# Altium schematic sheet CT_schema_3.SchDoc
size 293 x 258 mm
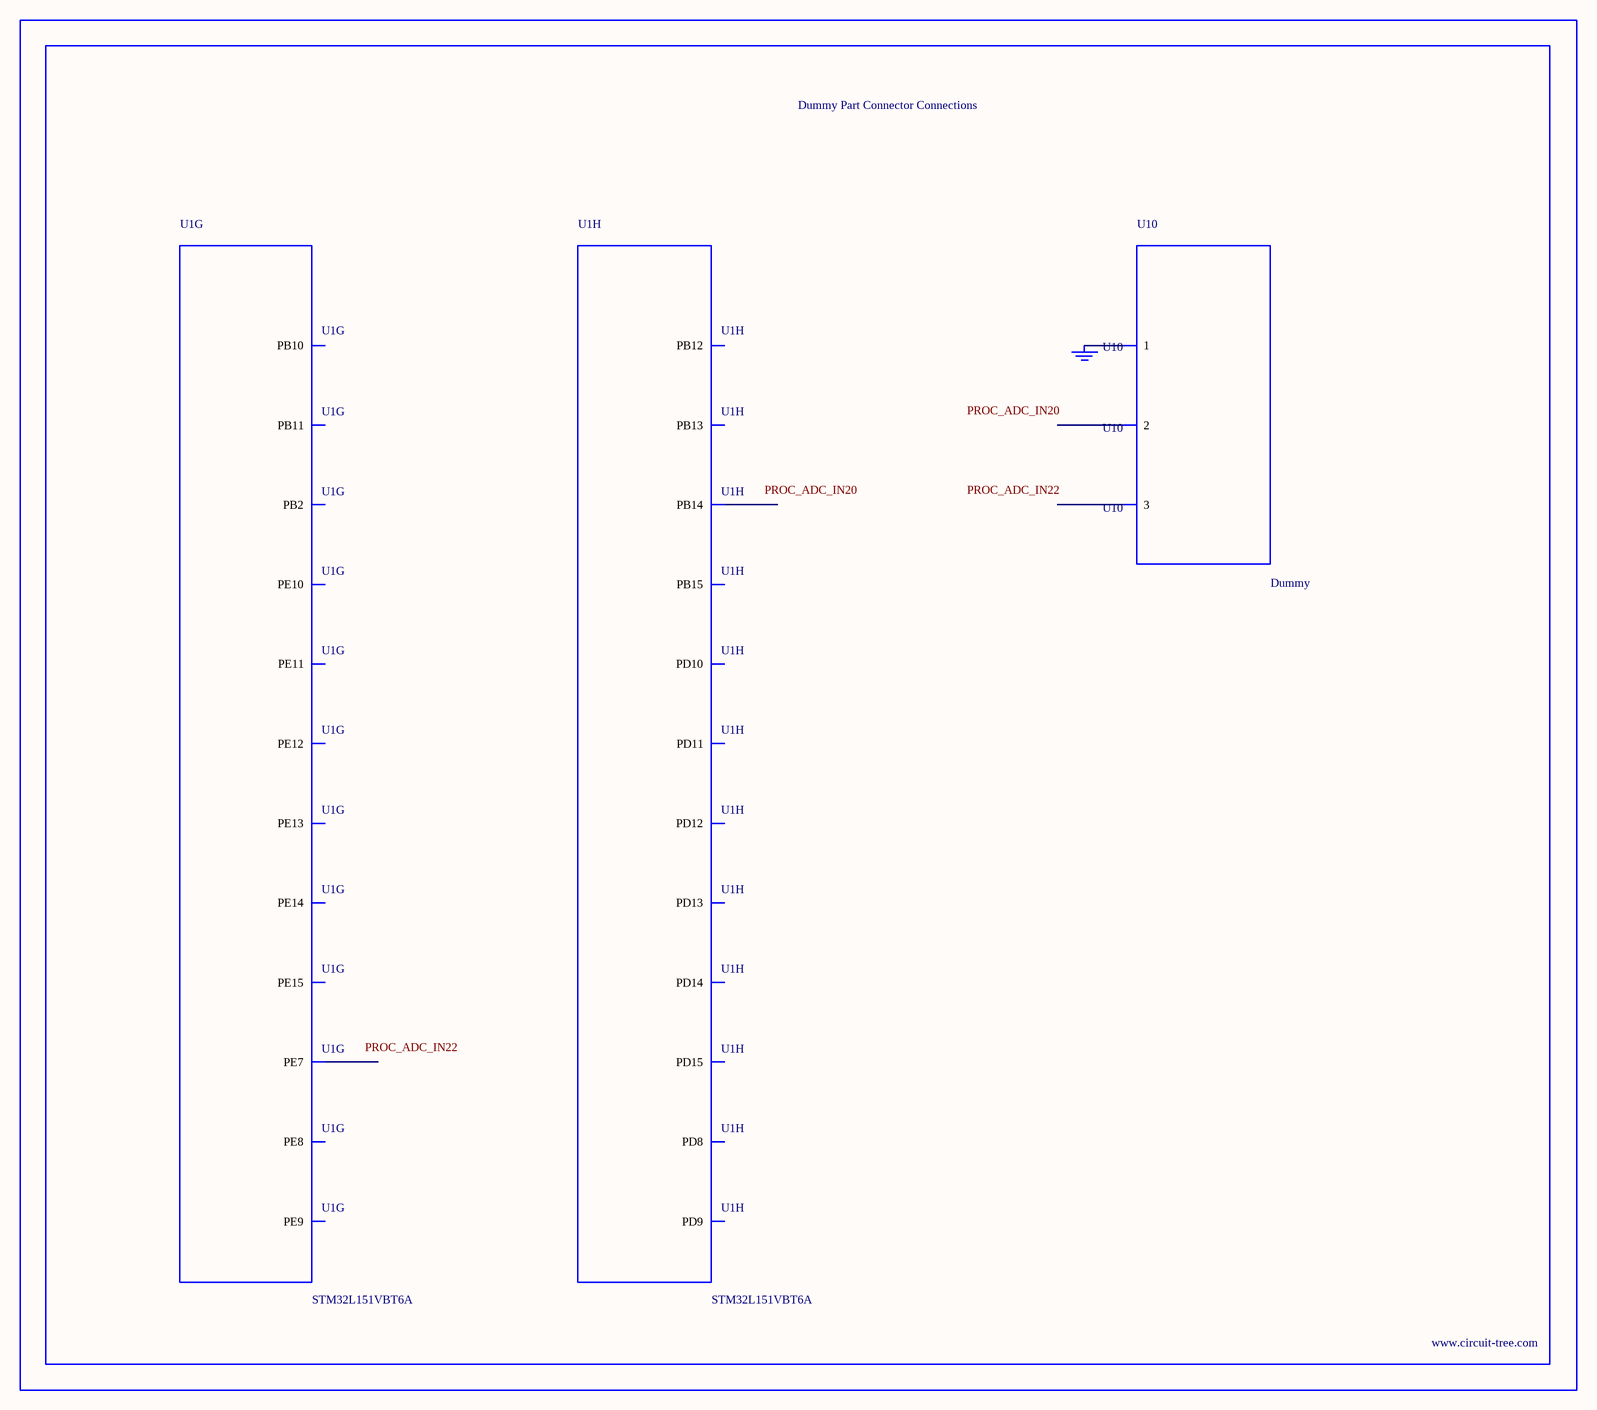
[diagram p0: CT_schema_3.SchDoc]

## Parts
BORDER2  (no value)
GND_INSTANCE_2_0  (no value)
U1  STM32L151VBT6A  [LQFP100]  (parts G,H of 8)
U10  Dummy  [DUMMY_PACKAGE_106]

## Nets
NetGND_INSTANCE_2_0_0: GND_INSTANCE_2_0.0(GND) U10.1

Not connected (* = marked no-connect by the designer): U1 37(PB2) 38(PE7) 39(PE8) 40(PE9) 41(PE10) 42(PE11) 43(PE12) 44(PE13) 45(PE14) 46(PE15) 47(PB10) 48(PB11) 51(PB12) 52(PB13) 53(PB14) 54(PB15) 55(PD8) 56(PD9) 57(PD10) 58(PD11) 59(PD12) 60(PD13) 61(PD14) 62(PD15); U10 2 3

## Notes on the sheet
- Labels drawn without touching a wire or pin: PROC_ADC_IN20, PROC_ADC_IN22

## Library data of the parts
BORDER2 = BORDER_PAGE2
GND_INSTANCE_2_0 = GND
